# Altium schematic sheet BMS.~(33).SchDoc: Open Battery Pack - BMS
size A3; Date: 26/03/2019; Author: Morgane Vallée - Samuel Lesueur; Revision: 1.0; SheetNumber: 1; SheetTotal: 3
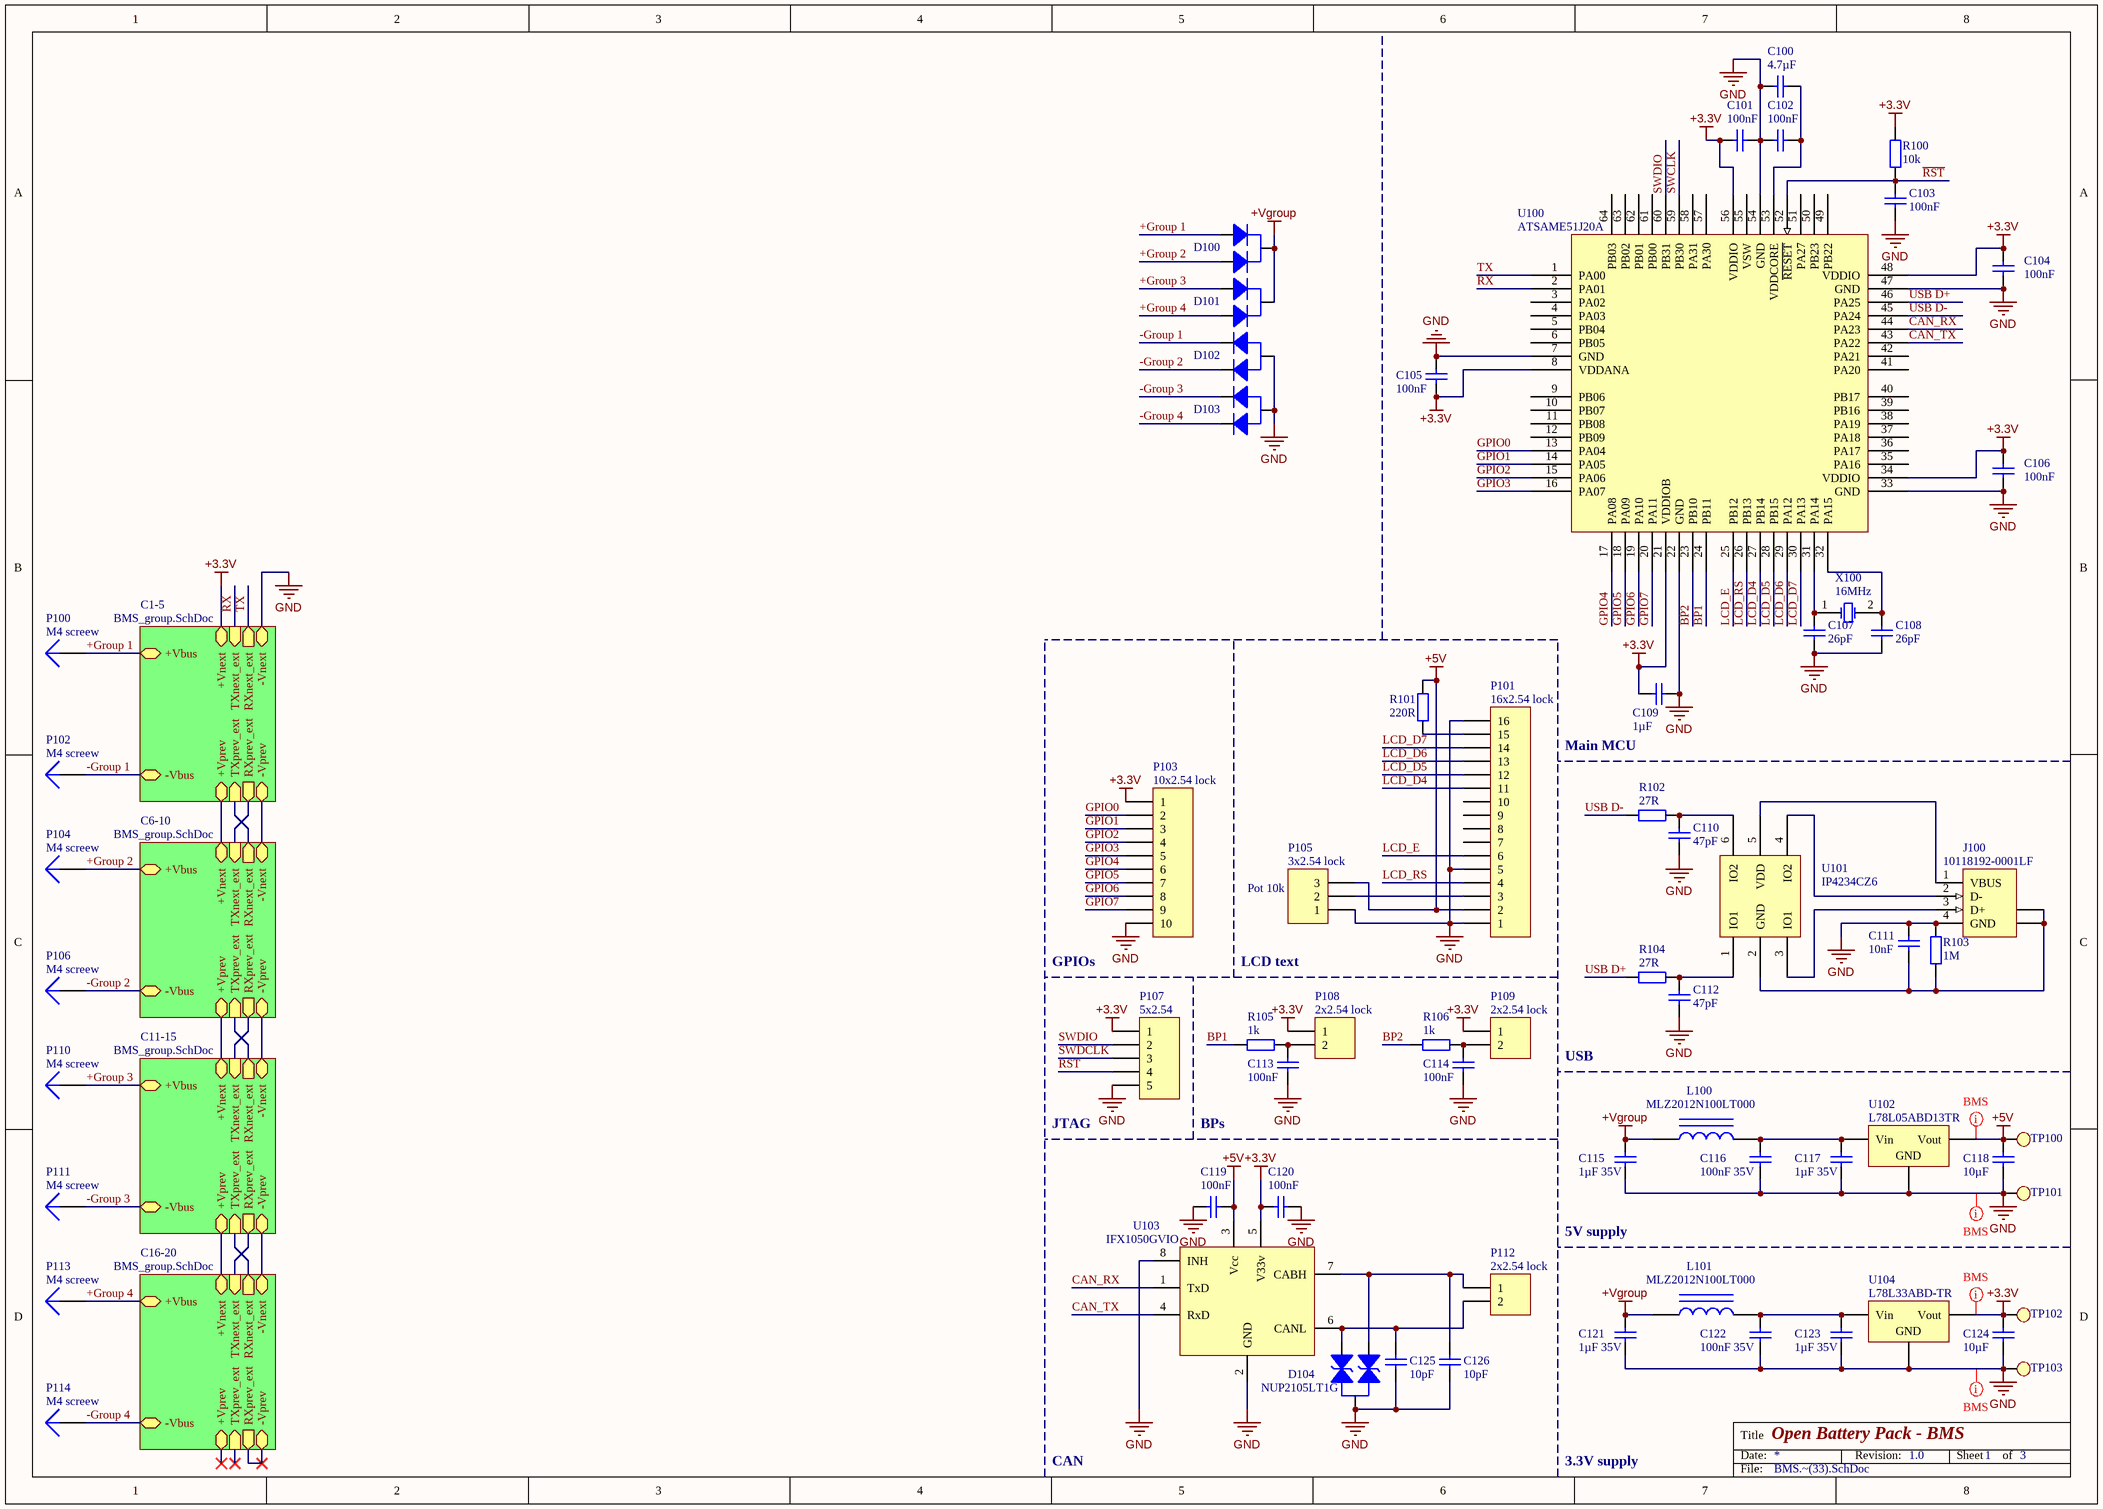
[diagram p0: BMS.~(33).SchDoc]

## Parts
C100  4.7µF  [C0603]
C101  100nF  [C0603]
C102  100nF  [C0603]
C103  100nF  [C0603]
C104  100nF  [C0603]
C105  100nF  [C0603]
C106  100nF  [C0603]
C107  26pF  [C0603]
C108  26pF  [C0603]
C109  1µF  [C0603]
C110  47pF  [C0603]
C111  10nF  [C0603]
C112  47pF  [C0603]
C113  100nF  [C0603]
C114  100nF  [C0603]
C115  1µF 35V  [C0603]
C116  100nF 35V  [C0603]
C117  1µF 35V  [C0603]
C118  10µF  [C0603]
C119  100nF  [C0603]
C120  100nF  [C0603]
C121  1µF 35V  [C0603]
C122  100nF 35V  [C0603]
C123  1µF 35V  [C0603]
C124  10µF  [C0603]
C125  10pF  [C0603]
C126  10pF  [C0603]
D100  (no value)  [DIODES SOT-23-3]
D101  (no value)  [DIODES SOT-23-3]
D102  (no value)  [DIODES SOT-23-3]
D103  (no value)  [DIODES SOT-23-3]
D104  NUP2105LT1G  [DIODES SOT-23-3]
J100  10118192-0001LF  [353576]
L100  MLZ2012N100LT000  [AXIAL-0.9]
L101  MLZ2012N100LT000  [AXIAL-0.9]
P100  M4 screew  [HOLE_4]
P101  16x2.54 lock  [HDR1X16]
P102  M4 screew  [HOLE_4]
P103  10x2.54 lock  [HDR1X10]
P104  M4 screew  [HOLE_4]
P105  3x2.54 lock  [MOLEX KK 0022272031]
P106  M4 screew  [HOLE_4]
P107  5x2.54  [HDR1X5]
P108  2x2.54 lock  [MOLEX KK 0022272021]
P109  2x2.54 lock  [MOLEX KK 0022272021]
P110  M4 screew  [HOLE_4]
P111  M4 screew  [HOLE_4]
P112  2x2.54 lock  [FCI 06-381-2PIN]
P113  M4 screew  [HOLE_4]
P114  M4 screew  [HOLE_4]
R100  10k  [R0603]
R101  220R  [R0603]
R102  27R  [R0603]
R103  1M  [R0603]
R104  27R  [R0603]
R105  1k  [R0603]
R106  1k  [R0603]
TP100  Test Point  [Test Point]  (value not drawn)
TP101  Test Point  [Test Point]  (value not drawn)
TP102  Test Point  [Test Point]  (value not drawn)
TP103  Test Point  [Test Point]  (value not drawn)
U100  ATSAME51J20A  [TQFP-64N]
U101  IP4234CZ6  [VISHAY TSOP-6 MO-193C]
U102  L78L05ABD13TR  [ST SOIC-8N]
U103  IFX1050GVIO  [INFINEON SO-8]
U104  L78L33ABD-TR  [ST SOIC-8N]
X100  16MHz  [ABRACON ABLS]

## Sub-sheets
C1-5 = BMS_group.SchDoc: -Vprev, RXnext_ext (out), +Vnext, -Vnext, TXnext_ext (in), RXprev_ext (out), +Vprev, TXprev_ext (in), -Vbus, +Vbus
C6-10 = BMS_group.SchDoc: -Vprev, RXnext_ext (out), +Vnext, -Vnext, TXnext_ext (in), RXprev_ext (out), +Vprev, TXprev_ext (in), -Vbus, +Vbus
C11-15 = BMS_group.SchDoc: -Vprev, RXnext_ext (out), +Vnext, -Vnext, TXnext_ext (in), RXprev_ext (out), +Vprev, TXprev_ext (in), -Vbus, +Vbus
C16-20 = BMS_group.SchDoc: -Vprev, RXnext_ext (out), +Vnext, -Vnext, TXnext_ext (in), RXprev_ext (out), +Vprev, TXprev_ext (in), -Vbus, +Vbus

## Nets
+3.3V: C101.2 C104.2 C105.1 C106.2 C109.2 C120.1 C124.1 P103.1 P107.1 P108.1 P109.1 R100.2 TP102.1 U100.8(VDDANA) U100.21(VDDIOB) U100.34(VDDIO) U100.48(VDDIO) U100.56(VDDIO) U103.5(V33v) U104.3(Vout) ; sheet C1-5/+Vnext
+5V: C118.1 C119.2 P101.2 P105.3 R101.2 TP100.1 U102.3(Vout) U103.3(Vcc)
+Vgroup: C115.1 C121.1 D100.3(K) D101.3(K) L100.1 L101.1
GND: C100.2 C101.1 C102.2 C103.1 C104.1 C105.2 C106.1 C107.1 C108.1 C109.1 C110.1 C111.2 C112.1 C113.1 C114.1 C115.2 C116.2 C117.2 C118.2 C119.1 C120.2 C121.2 C122.2 C123.2 C124.2 C125.1 C126.1 D102.3(A) D103.3(A) D104.3 J100.4(GND) P101.1 P101.5 P101.16 P103.10 P105.1 P107.5 R103.1 TP101.1 TP103.1 U100.7(GND) U100.22(GND) U100.33(GND) U100.47(GND) U100.54(GND) U102.2(GND) U103.2(GND) U103.8(INH) U104.2(GND) ; sheet C1-5/-Vnext
+Group 1: D100.1(A1) P100.1 ; sheet C1-5/+Vbus
+Group 2: D100.2(A2) P104.1 ; sheet C6-10/+Vbus
+Group 3: D101.1(A1) P110.1 ; sheet C11-15/+Vbus
+Group 4: D101.2(A2) P113.1 ; sheet C16-20/+Vbus
-Group 1: D102.2(K2) P102.1 ; sheet C1-5/-Vbus
-Group 2: D102.1(K1) P106.1 ; sheet C6-10/-Vbus
-Group 3: D103.2(K2) P111.1 ; sheet C11-15/-Vbus
-Group 4: D103.1(K1) P114.1 ; sheet C16-20/-Vbus
BP1: R105.1 U100.24(PB11)
BP2: R106.1 U100.23(PB10)
CAN_RX: U100.44(PA23) U103.1(TxD)
CAN_TX: U100.43(PA22) U103.4(RxD)
GPIO0: P103.2 U100.13(PA04)
GPIO1: P103.3 U100.14(PA05)
GPIO2: P103.4 U100.15(PA06)
GPIO3: P103.5 U100.16(PA07)
GPIO4: P103.6 U100.17(PA08)
GPIO5: P103.7 U100.18(PA09)
GPIO6: P103.8 U100.19(PA10)
GPIO7: P103.9 U100.20(PA11)
LCD_D4: P101.11 U100.27(PB14)
LCD_D5: P101.12 U100.28(PB15)
LCD_D6: P101.13 U100.29(PA12)
LCD_D7: P101.14 U100.30(PA13)
LCD_E: P101.6 U100.25(PB12)
LCD_RS: P101.4 U100.26(PB13)
~{RST}: C103.2 P107.4 R100.1 U100.52(~{RESET})
RX: U100.2(PA01) ; sheet C1-5/TXnext_ext
SWCLK: U100.59(PB30)
SWDCLK: P107.3
SWDIO: P107.2 U100.60(PB31)
TX: U100.1(PA00) ; sheet C1-5/RXnext_ext
USB D+: R104.1 U100.46(PA25)
USB D-: R102.1 U100.45(PA24)
NetC100_1: C100.1 C102.1 U100.53(VDDCORE)
NetC107_2: C107.2 U100.31(PA14) X100.1(OSC1)
NetC108_2: C108.2 U100.32(PA15) X100.2(OSC2)
NetC110_2: C110.2 R102.2 U101.6(IO2)
NetC111_1: C111.1 J100.5(SHLD) J100.6(SHLD) R103.2 U101.2(GND)
NetC112_2: C112.2 R104.2 U101.1(IO1)
NetC113_2: C113.2 P108.2 R105.2
NetC114_2: C114.2 P109.2 R106.2
NetC116_1: C116.1 C117.1 L100.2 U102.1(Vin)
NetC122_1: C122.1 C123.1 L101.2 U104.1(Vin)
NetC125_2: C125.2 D104.2 P112.2 U103.6(CANL)
NetC126_2: C126.2 D104.1 P112.1 U103.7(CABH)
NetJ100_1: J100.1(VBUS) U101.5(VDD)
NetJ100_2: J100.2(D-) U101.4(IO2)
NetJ100_3: J100.3(D+) U101.3(IO1)
NetP101_3: P101.3 P105.2
NetP101_15: P101.15 R101.1
(unnamed): sheet C1-5/-Vprev, sheet C6-10/-Vnext
(unnamed): sheet C1-5/RXprev_ext, sheet C6-10/TXnext_ext  [a separate net that carries the same name]
(unnamed): sheet C1-5/+Vprev, sheet C6-10/+Vnext  [a separate net that carries the same name]
(unnamed): sheet C1-5/TXprev_ext, sheet C6-10/RXnext_ext  [a separate net that carries the same name]
(unnamed): sheet C6-10/-Vprev, sheet C11-15/-Vnext  [a separate net that carries the same name]
(unnamed): sheet C6-10/RXprev_ext, sheet C11-15/TXnext_ext  [a separate net that carries the same name]
(unnamed): sheet C6-10/+Vprev, sheet C11-15/+Vnext  [a separate net that carries the same name]
(unnamed): sheet C6-10/TXprev_ext, sheet C11-15/RXnext_ext  [a separate net that carries the same name]
(unnamed): sheet C11-15/-Vprev, sheet C16-20/-Vnext  [a separate net that carries the same name]
(unnamed): sheet C11-15/RXprev_ext, sheet C16-20/TXnext_ext  [a separate net that carries the same name]
(unnamed): sheet C11-15/+Vprev, sheet C16-20/+Vnext  [a separate net that carries the same name]
(unnamed): sheet C11-15/TXprev_ext, sheet C16-20/RXnext_ext  [a separate net that carries the same name]
(unnamed): sheet C16-20/-Vprev, sheet C16-20/RXprev_ext  [a separate net that carries the same name]

Not connected (* = marked no-connect by the designer): P101 7 8 9 10; U100 3(PA02) 4(PA03) 5(PB04) 6(PB05) 9(PB06) 10(PB07) 11(PB08) 12(PB09) 35(PA16) 36(PA17) 37(PA18) 38(PA19) 39(PB16) 40(PB17) 41(PA20) 42(PA21) 49(PB22) 50(PB23) 51(PA27) 55(VSW) 57(PA30) 58(PA31) 61(PB00) 62(PB01) 63(PB02) 64(PB03)

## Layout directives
net class BMS: +3.3V, +5V, GND

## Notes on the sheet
- Main MCU
- (near P105) Pot 10k
- GPIOs
- LCD text
- JTAG
- BPs
- USB
- 5V supply
- CAN
- 3.3V supply

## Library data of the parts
C100-C126 = Cap: Capacitor
D100 D101 = Diode dual C: Diode 2 common Cathode
D102 D103 = Diode dual A: Diode 2 common Anode
D104 = Dual Line TVS
J100 = 1-353576-1: USB 1.1, Right Angle, SMT, A Type, Receptacle, 4 Position, White
L100 L101 = Inductor Iron: Magnetic-Core Inductor
P100 P102 P104 P106 P110 P111 P113 P114 = Plug
P101 = Header 16: Header, 16-Pin
P103 = Header 10: Header, 10-Pin
P105 = Header 3: Header, 3-Pin
P107 = Header 5: Header, 5-Pin
P108 P109 = Header 2: Header, 2-Pin
P112 = Header 2H: Header, 2-Pin, Right Angle
R100-R106 = Res2: Resistor
U101 = IP4234CZ6: Single USB 2.0 ESD protection to IEC 61000-4-2 level 4
U102 U104 = Volt Reg: Voltage Regulator; pin to pad: 1>8 2>2+3+6+7 3>1
U103 = IFX1050GVIO: High Speed CAN-Transceiver
X100 = XTAL: Crystal Oscillator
